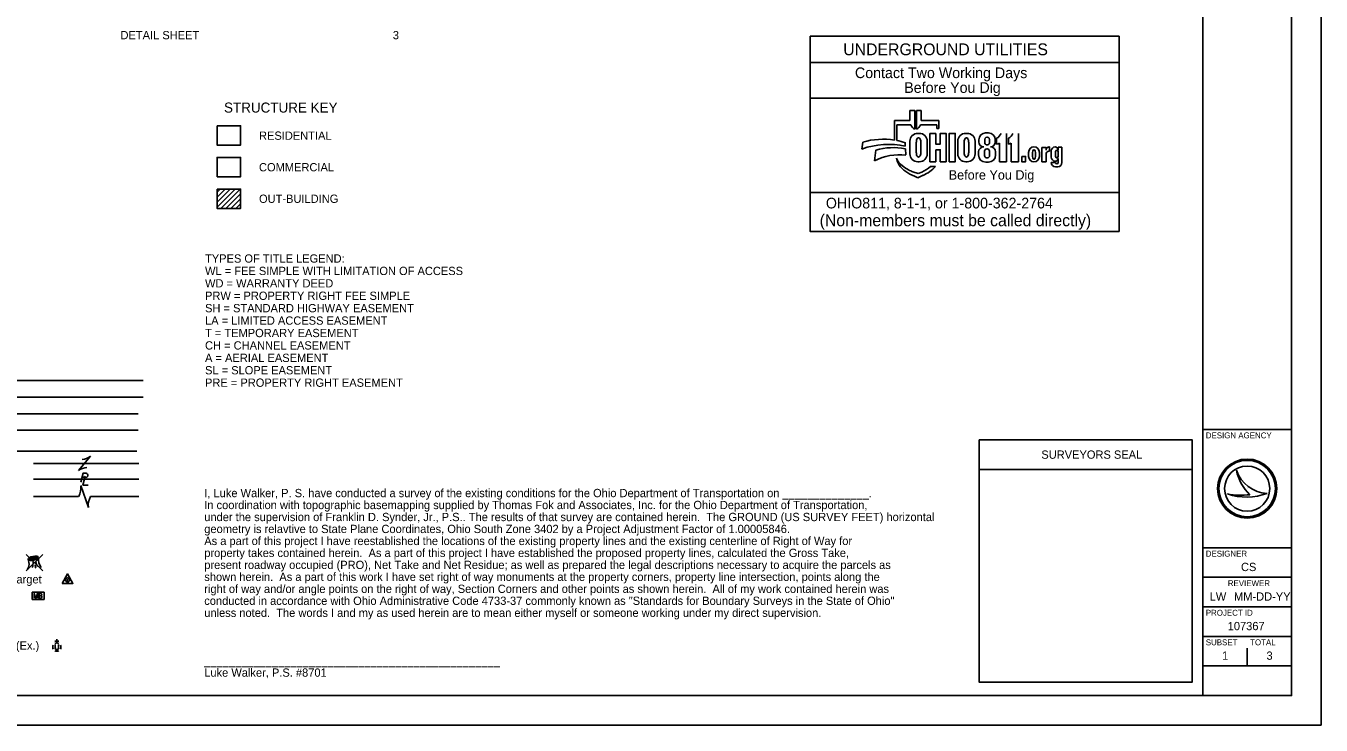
# Model space of a CAD drawing. Extents: x 0 to 34, y 0 to 22.
# Drawn here: x 12.09 to 34, y 0 to 11.83 of the extents above; entities that cross this region are included whole.
import ezdxf

# ---------------------------------------------------------------- set-up
doc = ezdxf.new("R2010")
doc.units = 0
for name, color, linetype in [('SC_Shading1', 7, 'Continuous'), ('SH_Border', 7, 'Continuous'), ('SH_Cut_Line', 7, 'Continuous'), ('SH_Data', 7, 'Continuous'), ('SH_Text', 7, 'Continuous')]:
    doc.layers.add(name, color=color, linetype=linetype)

msp = doc.modelspace()

# ---------------------------------------------------------------- linework, layer by layer
at = {"layer": 'SC_Shading1'}
msp.add_lwpolyline([(15.326, 9.275), (15.723, 9.275), (15.723, 9.601), (15.326, 9.601)], close=True, dxfattribs=at)
at = {"layer": 'SH_Border'}
for p, q in [((32, 0.5), (32, 21.5)), ((32, 5), (33.5, 5)), ((32, 3), (33.5, 3)), ((32, 2.5), (33.5, 2.5)), ((32, 2), (33.5, 2)), ((32, 1.5), (33.5, 1.5)), ((32, 1), (33.5, 1))]:
    msp.add_line(p, q, dxfattribs=at)
msp.add_lwpolyline([(1.5, 21.5), (33.5, 21.5), (33.5, 0.5), (1.5, 0.5)], close=True, dxfattribs=at)
at = {"layer": 'SH_Cut_Line'}
msp.add_lwpolyline([(0, 0), (34, 0), (34, 22), (0, 22)], close=True, dxfattribs=at)
at = {"layer": 'SH_Data'}
for p, q in [((27.126, 10.396), (27.046, 10.396)), ((27.046, 10.396), (27.046, 10.229)), ((27.126, 10.079), (27.126, 10.396)), ((27.237, 10.396), (27.157, 10.396)), ((27.157, 10.396), (27.157, 10.079)), ((27.237, 10.229), (27.237, 10.396)), ((27.046, 10.229), (26.783, 10.229)), ((26.783, 10.229), (26.783, 9.895)), ((26.821, 9.888), (26.821, 10.153)), ((26.821, 10.153), (27.062, 10.153)), ((27.222, 10.153), (27.5, 10.153)), ((27.535, 10.229), (27.237, 10.229)), ((27.5, 10.153), (27.5, 10.089)), ((27.5, 10.089), (27.535, 10.089)), ((27.535, 10.089), (27.535, 10.229)), ((26.248, 9.861), (26.234, 9.744)), ((27.044, 9.875), (27.044, 9.662)), ((27.153, 9.679), (27.153, 9.862)), ((27.203, 10.008), (27.178, 10.008)), ((27.228, 9.862), (27.228, 9.679)), ((27.336, 9.662), (27.336, 9.875)), ((27.481, 10.007), (27.379, 10.007)), ((27.379, 10.007), (27.379, 9.529)), ((27.855, 9.875), (27.855, 9.662)), ((27.964, 9.679), (27.964, 9.862)), ((28.014, 10.008), (27.989, 10.008)), ((28.039, 9.862), (28.039, 9.679)), ((28.147, 9.662), (28.147, 9.875)), ((28.212, 9.901), (28.212, 9.864)), ((28.311, 9.847), (28.311, 9.906)), ((28.375, 10.015), (28.326, 10.015)), ((28.392, 9.906), (28.392, 9.847)), ((28.489, 9.864), (28.489, 9.901)), ((28.512, 9.826), (28.512, 9.928)), ((28.678, 10.007), (28.678, 9.529)), ((28.712, 9.826), (28.712, 9.928)), ((28.879, 10.007), (28.879, 9.529)), ((26.469, 9.725), (26.447, 9.546)), ((26.967, 9.793), (26.967, 9.851)), ((26.977, 9.643), (26.968, 9.749)), ((27.481, 9.529), (27.481, 9.731)), ((28.206, 9.694), (28.206, 9.643)), ((28.307, 9.635), (28.307, 9.696)), ((28.392, 9.696), (28.392, 9.635)), ((28.495, 9.643), (28.495, 9.694)), ((28.56, 9.529), (28.56, 9.84)), ((28.76, 9.529), (28.76, 9.84)), ((29.052, 9.62), (29.052, 9.687)), ((29.12, 9.618), (29.12, 9.687)), ((29.168, 9.687), (29.168, 9.618)), ((29.235, 9.687), (29.235, 9.62)), ((29.347, 9.772), (29.274, 9.772)), ((29.274, 9.772), (29.274, 9.529)), ((29.347, 9.725), (29.347, 9.772)), ((29.347, 9.529), (29.347, 9.656)), ((29.397, 9.705), (29.408, 9.705)), ((29.408, 9.78), (29.402, 9.78)), ((29.408, 9.705), (29.408, 9.78)), ((29.436, 9.607), (29.436, 9.711)), ((29.508, 9.621), (29.508, 9.697)), ((29.551, 9.727), (29.551, 9.774)), ((29.551, 9.774), (29.616, 9.774)), ((29.551, 9.697), (29.551, 9.621)), ((29.616, 9.774), (29.616, 9.515)), ((26.82, 9.589), (26.824, 9.562)), ((27.178, 9.529), (27.203, 9.529)), ((27.379, 9.529), (27.481, 9.529)), ((27.478, 9.449), (27.393, 9.449)), ((27.476, 9.446), (27.478, 9.449)), ((27.989, 9.529), (28.014, 9.529)), ((28.327, 9.523), (28.374, 9.523)), ((28.678, 9.529), (28.56, 9.529)), ((28.879, 9.529), (28.76, 9.529)), ((29.274, 9.529), (29.347, 9.529)), ((29.436, 9.515), (29.508, 9.515)), ((29.546, 9.445), (29.506, 9.445)), ((29.551, 9.515), (29.551, 9.585)), ((27.185, 9.328), (27.096, 9.359)), ((27.12, 9.282), (27.176, 9.258)), ((27.176, 9.258), (27.27, 9.299)), ((27.246, 9.355), (27.185, 9.328)), ((30.582, 8.35), (25.357, 8.35)), ((28.219, 4.325), (31.819, 4.325)), ((32.567, 4.31), (32.567, 4.31)), ((32.75, 4), (32.75, 4)), ((32.417, 3.91), (32.417, 3.91)), ((33.087, 3.919), (33.087, 3.919)), ((32.75, 1), (32.75, 1.3))]:
    msp.add_line(p, q, dxfattribs=at)
for points in [[(25.357, 11.65), (30.582, 11.65), (30.582, 11.21), (25.357, 11.21)], [(25.357, 11.21), (30.582, 11.21), (30.582, 10.605), (25.357, 10.605)], [(25.357, 10.605), (30.582, 10.605), (30.582, 9.01), (25.357, 9.01)], [(28.937, 9.618), (29.002, 9.618), (29.002, 9.529), (28.937, 9.529)], [(25.357, 9.01), (30.582, 9.01), (30.582, 8.35), (25.357, 8.35)], [(28.219, 4.825), (31.819, 4.825), (31.819, 0.725), (28.219, 0.725)]]:
    msp.add_lwpolyline(points, close=True, dxfattribs=at)
for points in [[(27.481, 9.731), (27.557, 9.731), (27.557, 9.529), (27.658, 9.529), (27.658, 10.007), (27.557, 10.007), (27.557, 9.826), (27.481, 9.826), (27.481, 10.007)], [(27.709, 9.529), (27.812, 9.529), (27.812, 10.007), (27.709, 10.007), (27.709, 9.529)], [(28.293, 9.781), (28.293, 9.781)], [(28.408, 9.781), (28.408, 9.781)]]:
    msp.add_lwpolyline(points, dxfattribs=at)
for radius in [0.5, 0.477, 0.477, 0.382]:
    msp.add_circle((32.75, 4), radius, dxfattribs=at)
for centre, radius, start, end in [((27.198, 10.207), 0.147, 201.9296, 240.7469), ((27.085, 10.207), 0.147, 299.2531, 338.0704), ((26.592, 8.686), 1.224, 81.0007, 106.3144), ((26.592, 8.686), 1.224, 72.1402, 79.2074), ((27.178, 9.875), 0.134, 90, 180), ((27.203, 9.875), 0.134, 0, 90), ((27.989, 9.875), 0.134, 90, 180), ((28.014, 9.875), 0.134, 0, 90), ((28.326, 9.901), 0.114, 90, 180), ((28.295, 9.864), 0.0837, 180, 268.1442), ((28.375, 9.901), 0.114, 0, 90), ((28.405, 9.864), 0.0837, 272.2058, 0), ((28.461, 10.05), 0.132, 292.5572, 340.7355), ((28.661, 10.05), 0.132, 292.5572, 340.7355), ((26.686, 8.491), 1.332, 77.8238, 109.8274), ((26.875, 8.698), 0.95, 83.8248, 116.8021), ((26.767, 8.673), 1.094, 79.44, 105.8467), ((27.178, 9.662), 0.134, 180, 270), ((27.203, 9.662), 0.134, 270, 0), ((27.989, 9.662), 0.134, 180, 270), ((28.014, 9.662), 0.134, 270, 0), ((28.293, 9.694), 0.0865, 90, 180), ((28.327, 9.643), 0.121, 180, 270), ((28.374, 9.643), 0.121, 270, 0), ((28.408, 9.694), 0.0865, 0, 90), ((28.5, 9.958), 0.132, 275.1733, 297.0931), ((28.7, 9.958), 0.132, 275.1733, 297.0931), ((29.148, 9.687), 0.0956, 92.5886, 180), ((29.139, 9.687), 0.0956, 0, 87.4114), ((29.402, 9.725), 0.0548, 90, 180), ((29.397, 9.656), 0.0493, 90, 180), ((29.505, 9.711), 0.0686, 92.6865, 180), ((29.499, 9.727), 0.0524, 0, 86.9262), ((27.1, 9.697), 0.3, 201.0457, 232.5314), ((27.036, 9.598), 0.214, 189.6817, 216.0884), ((27.235, 9.744), 0.461, 216.0884, 235.7167), ((27.387, 10.072), 0.773, 232.5314, 241.794), ((27.032, 9.848), 0.538, 293.4582, 312.0712), ((27.032, 9.848), 0.599, 293.4582, 317.8286), ((29.148, 9.62), 0.0956, 180, 267.4114), ((29.139, 9.62), 0.0956, 272.5886, 0), ((29.505, 9.607), 0.0692, 180, 265.7132), ((29.506, 9.515), 0.0699, 180, 270), ((29.505, 9.585), 0.0467, 264.7825, 0), ((29.546, 9.515), 0.0699, 270, 0), ((27.484, 10.109), 0.903, 235.7167, 246.2325), ((27.26, 9.835), 0.504, 241.794, 250.9821), ((33.116, 4.498), 0.58, 198.9257, 198.9319), ((33.347, 4.47), 0.796, 191.6379, 191.6421), ((33.116, 4.498), 0.58, 198.9319, 267.1657), ((33.347, 4.47), 0.796, 191.6421, 226.0947), ((32.739, 4.87), 1.013, 251.4576, 290.0832), ((32.648, 5.154), 1.266, 259.4964, 259.4995), ((32.739, 4.87), 1.013, 251.4527, 251.4576), ((32.648, 5.154), 1.266, 259.4995, 276.6672)]:
    msp.add_arc(centre, radius, start, end, dxfattribs=at)
for centre, major_axis, ratio, start_param, end_param in [((27.191, 9.862), (0, 0.0723), 0.514403, 4.712389, 7.853982), ((28.001, 9.862), (0, 0.0723), 0.514403, 4.712389, 7.853982), ((28.351, 9.906), (0.0404, 0), 0.969373, 0, 3.141593), ((27.191, 9.679), (0, 0.0723), 0.514403, 1.570796, 4.712389), ((28.001, 9.679), (0, 0.0723), 0.514403, 1.570796, 4.712389), ((28.35, 9.696), (0, 0.0535), 0.794529, 4.712389, 7.853982), ((28.351, 9.847), (0.0404, 0), 0.818453, 3.141593, 6.283185), ((29.144, 9.687), (0, 0.0434), 0.553236, 4.712389, 7.853982), ((29.53, 9.697), (0, 0.0275), 0.777179, 4.712389, 7.853982), ((28.35, 9.635), (0.0425, 0), 0.959837, 3.141593, 6.283185), ((29.144, 9.618), (0, 0.046), 0.522014, 1.570796, 4.712389), ((29.53, 9.621), (0, 0.0275), 0.777179, 1.570796, 4.712389), ((29.53, 9.515), (0.0214, 0), 0.959012, 3.141593, 6.283185)]:
    msp.add_ellipse(centre, major_axis=major_axis, ratio=ratio, start_param=start_param, end_param=end_param, dxfattribs=at)
at = {"layer": 'SH_Text'}
for p, q in [((15.326, 9.064), (15.327, 9.066)), ((15.326, 9.014), (15.377, 9.066)), ((15.326, 8.93), (15.462, 9.066)), ((15.326, 8.845), (15.546, 9.066)), ((15.326, 8.76), (15.631, 9.066)), ((15.39, 8.74), (15.716, 9.066)), ((15.475, 8.74), (15.723, 8.988)), ((15.559, 8.74), (15.723, 8.903)), ((15.644, 8.74), (15.723, 8.818)), ((15.326, 8.744), (15.33, 8.74)), ((10.589, 5.826), (14.073, 5.826)), ((10.589, 5.546), (14.073, 5.546)), ((10.089, 5.266), (13.989, 5.266)), ((10.089, 4.986), (13.989, 4.986)), ((9.621, 4.636), (13.971, 4.636)), ((12.219, 4.426), (14.001, 4.426)), ((12.984, 4.306), (13.184, 4.546)), ((13.084, 4.426), (13.084, 4.426)), ((13.042, 4.191), (13.107, 4.191)), ((12.219, 4.161), (14.001, 4.161)), ((13.019, 4.05), (13.149, 3.682)), ((13.082, 4.16), (13.082, 4.16)), ((12.219, 3.866), (12.984, 3.866)), ((13.084, 3.866), (13.084, 3.866)), ((13.184, 3.866), (14.001, 3.866)), ((12.098, 2.885), (12.376, 2.607)), ((12.376, 2.885), (12.098, 2.607)), ((12.237, 2.746), (12.237, 2.746)), ((12.237, 2.746), (12.237, 2.746)), ((12.298, 2.186), (12.298, 2.186)), ((12.647, 1.421), (12.583, 1.421)), ((12.588, 1.362), (12.588, 1.294)), ((12.615, 1.389), (12.615, 1.453)), ((12.615, 1.319), (12.615, 1.319)), ((12.642, 1.362), (12.642, 1.294))]:
    msp.add_line(p, q, dxfattribs=at)
for points in [[(15.326, 10.136), (15.723, 10.136), (15.723, 9.811), (15.326, 9.811)], [(15.326, 9.066), (15.723, 9.066), (15.723, 8.74), (15.326, 8.74)], [(12.706, 2.396), (12.886, 2.396), (12.796, 2.557)], [(12.198, 2.247), (12.398, 2.247), (12.398, 2.125), (12.198, 2.125)]]:
    msp.add_lwpolyline(points, close=True, dxfattribs=at)
for points in [[(13.021, 4.111), (13.06, 4.259), (13.112, 4.259)], [(13.095, 4.208), (13.056, 4.06), (13.143, 4.06)], [(12.233, 2.146), (12.233, 2.226), (12.262, 2.146), (12.29, 2.226), (12.29, 2.146)], [(12.349, 2.189), (12.352, 2.192), (12.354, 2.194), (12.355, 2.196), (12.356, 2.197), (12.357, 2.2), (12.358, 2.202), (12.359, 2.206), (12.359, 2.208), (12.359, 2.211), (12.358, 2.214), (12.357, 2.218), (12.355, 2.22), (12.352, 2.223), (12.35, 2.224), (12.348, 2.225), (12.345, 2.226), (12.314, 2.226), (12.314, 2.146), (12.349, 2.146), (12.353, 2.148), (12.357, 2.151), (12.36, 2.156), (12.362, 2.162), (12.363, 2.168), (12.363, 2.172), (12.362, 2.175), (12.359, 2.181), (12.356, 2.185), (12.349, 2.189), (12.314, 2.189)]]:
    msp.add_lwpolyline(points, dxfattribs=at)
for radius in [0.035, 0.008]:
    msp.add_circle((12.796, 2.454), radius, dxfattribs=at)
for centre, radius, start, end in [((13.026, 4.761), 0.267, 273.6945, 306.337), ((13.142, 4.091), 0.267, 93.6945, 126.337), ((13.107, 4.225), 0.0345, 270.471, 81.3281), ((12.687, 4.017), 0.334, 332.9422, 5.5848), ((13.481, 3.714), 0.334, 152.9422, 185.5848), ((11.945, 2.728), 0.2, 331.5338, 20.9269), ((11.961, 2.747), 0.253, 340.7938, 3.5481), ((12.432, 2.706), 0.182, 178.7926, 197.1224), ((12.562, 2.849), 0.316, 194.9653, 212.1216), ((12.517, 2.803), 0.215, 171.4106, 219.9194), ((12.615, 1.319), 0.07, 150.0184, 209.9816), ((12.615, 1.319), 0.07, 60.0184, 120.0157), ((12.615, 1.319), 0.07, 330.0184, 29.9816), ((12.615, 1.319), 0.07, 239.9843, 299.9816), ((12.615, 1.306), 0.03, 205.1924, 334.8076)]:
    msp.add_arc(centre, radius, start, end, dxfattribs=at)
for major_axis in [(0.0868, 0.0187), (0.0651, 0.0141), (0.0488, 0.0105), (0.0275, 0.0059), (0.0154, 0.0033)]:
    msp.add_ellipse((12.218, 2.821), major_axis=major_axis, ratio=0.36865, dxfattribs=at)

# ---------------------------------------------------------------- texts
at = {"layer": 'SH_Data'}
for s, height, p in [('DETAIL SHEET', 0.14, (13.692, 11.6)), ('     3', 0.14, (18.038, 11.6)), ('UNDERGROUND UTILITIES', 0.2, (25.917, 11.33)), ('Contact Two Working Days', 0.18, (26.115, 10.943)), ('Before You Dig', 0.18, (26.949, 10.693)), ('Before You Dig', 0.15972, (27.701, 9.226)), ('OHIO811, 8-1-1, or 1-800-362-2764', 0.18, (25.623, 8.739)), ('(Non-members must be called directly)', 0.2, (25.518, 8.438)), ('DESIGN AGENCY', 0.1, (32.05, 4.85)), ('SURVEYORS SEAL', 0.14, (29.268, 4.505)), ('I, Luke Walker, P. S. have conducted a survey of the existing conditions for the Ohio Department of Transportation on ______________.', 0.14, (15.109, 3.855)), ('In coordination with topographic basemapping supplied by Thomas Fok and Associates, Inc. for the Ohio Department of Transportation,', 0.14, (15.109, 3.653)), ('under the supervision of Franklin D. Synder, Jr., P.S.. The results of that survey are contained herein.  The GROUND (US SURVEY FEET) horizontal ', 0.14, (15.109, 3.45)), ('geometry is relavtive to State Plane Coordinates, Ohio South Zone 3402 by a Project Adjustment Factor of 1.00005846.', 0.14, (15.109, 3.248)), ('As a part of this project I have reestablished the locations of the existing property lines and the existing centerline of Right of Way for ', 0.14, (15.109, 3.045)), ('property takes contained herein.  As a part of this project I have established the proposed property lines, calculated the Gross Take, ', 0.14, (15.109, 2.843)), ('DESIGNER', 0.1, (32.05, 2.85)), ('present roadway occupied (PRO), Net Take and Net Residue; as well as prepared the legal descriptions necessary to acquire the parcels as ', 0.14, (15.109, 2.64)), ('CS', 0.14, (32.645, 2.605)), ('shown herein.  As a part of this work I have set right of way monuments at the property corners, property line intersection, points along the ', 0.14, (15.109, 2.438)), ('REVIEWER', 0.1, (32.422, 2.35)), ('right of way and/or angle points on the right of way, Section Corners and other points as shown herein.  All of my work contained herein was ', 0.14, (15.109, 2.235)), ('LW', 0.14, (32.115, 2.105)), ('MM-DD-YY', 0.14, (32.527, 2.105)), ('conducted in accordance with Ohio Administrative Code 4733-37 commonly known as "Standards for Boundary Surveys in the State of Ohio" ', 0.14, (15.109, 2.033)), ('unless noted.  The words I and my as used herein are to mean either myself or someone working under my direct supervision.', 0.14, (15.109, 1.83)), ('PROJECT ID', 0.1, (32.05, 1.85)), ('107367', 0.14, (32.42, 1.605)), ('SUBSET', 0.1, (32.05, 1.35)), ('TOTAL', 0.1, (32.8, 1.35)), ('1', 0.14, (32.325, 1.105)), ('3', 0.14, (33.076, 1.105)), ('________________________________________________', 0.14, (15.109, 1.02)), ('Luke Walker, P.S. #8701', 0.14, (15.109, 0.818))]:
    msp.add_text(s, height=height, dxfattribs=at).set_placement(p)
at = {"layer": 'SH_Text'}
for s, height, p in [('STRUCTURE KEY', 0.17, (15.443, 10.36)), ('RESIDENTIAL', 0.14, (16.035, 9.9)), ('COMMERCIAL', 0.14, (16.035, 9.366)), ('OUT-BUILDING', 0.14, (16.035, 8.833)), ('TYPES OF TITLE LEGEND:', 0.14, (15.122, 7.822)), ('WL = FEE SIMPLE WITH LIMITATION OF ACCESS', 0.14, (15.122, 7.612)), ('WD = WARRANTY DEED', 0.14, (15.122, 7.402)), ('PRW = PROPERTY RIGHT FEE SIMPLE', 0.14, (15.122, 7.192)), ('SH = STANDARD HIGHWAY EASEMENT', 0.14, (15.122, 6.982)), ('LA = LIMITED ACCESS EASEMENT', 0.14, (15.122, 6.772)), ('T = TEMPORARY EASEMENT', 0.14, (15.122, 6.562)), ('CH = CHANNEL EASEMENT', 0.14, (15.122, 6.352)), ('A = AERIAL EASEMENT', 0.14, (15.122, 6.142)), ('SL = SLOPE EASEMENT', 0.14, (15.122, 5.932)), ('PRE = PROPERTY RIGHT EASEMENT', 0.14, (15.122, 5.722)), ('Wetland (Pr)         , Grass (Pr)            , Aerial Target    ', 0.14, (8.073, 2.396)), ('Water Valve (Ex)         , Utility Valve Unknown (Ex.)', 0.14, (8.073, 1.276))]:
    msp.add_text(s, height=height, dxfattribs=at).set_placement(p)

doc.saveas('drawing.dxf')
